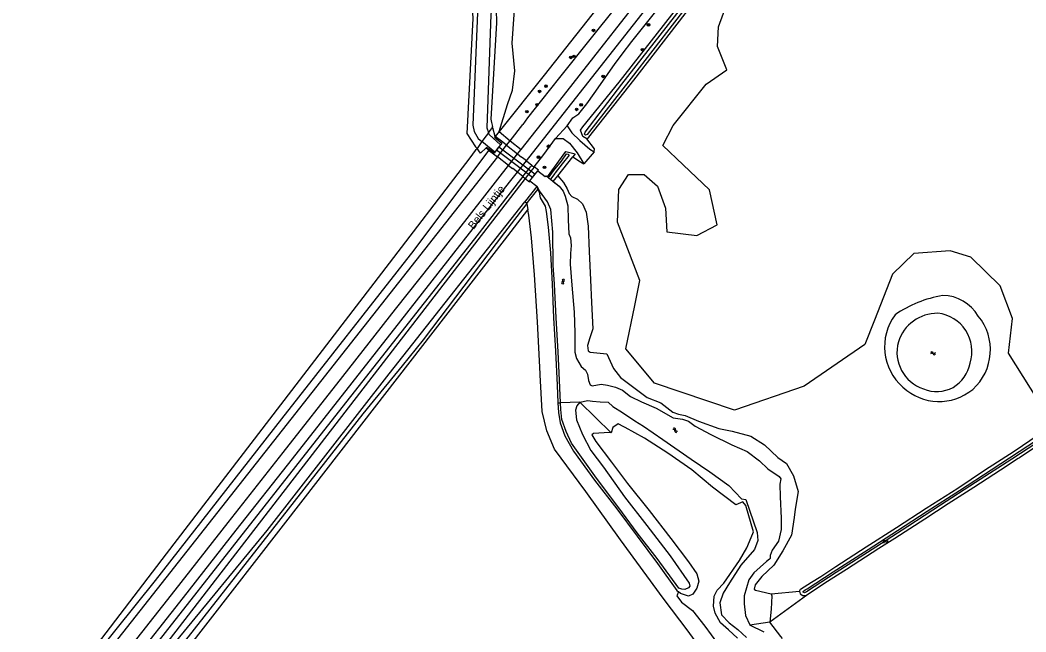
# Model space of a CAD drawing. Extents: x 126000 to 131009, y 393000 to 395500.
# Drawn here: x 129887 to 130201.2, y 393741.6 to 393932.5 of the extents above; entities that cross this region are included whole.
import ezdxf

# ---------------------------------------------------------------- set-up
doc = ezdxf.new("R2010")
doc.units = 0
for name, color, linetype in [('gg-afsc-hekwerk', 7, 'Continuous'), ('gg-anno-openbare ruimte label', 7, 'Continuous'), ('gg-knt-BGT kruinlijn', 7, 'Continuous'), ('gg-knt-bovenkant onderkant talud', 7, 'Continuous'), ('gg-knt-bronhoudergrens', 7, 'Continuous'), ('gg-kntw-bovenkant insteek waterloop', 7, 'Continuous'), ('gg-kntw-waterlijn', 7, 'Continuous'), ('gg-kwrk-duiker nz vlak', 7, 'Continuous'), ('gt-grn-groengrens', 7, 'Continuous'), ('gt-symb-boom', 7, 'Continuous'), ('gt-symb-watersymbool', 7, 'Continuous'), ('gx-grn-maaiveld', 7, 'Continuous')]:
    doc.layers.add(name, color=color, linetype=linetype)

# ---------------------------------------------------------------- blocks, each defined once
blk = doc.blocks.new('gt0-WA')
at = {"layer": 'gt-symb-watersymbool'}
for centre, start, end in [((-0.32, 0.02), 28.0725, 151.9275), ((0.43, 0.42), 208.0725, 331.9275), ((-0.32, -0.43), 28.0725, 151.9275), ((0.43, -0.03), 208.0725, 331.9275)]:
    blk.add_arc(centre, 0.425, start, end, dxfattribs=at)
blk = doc.blocks.new('gt0-BOOM')
at = {"layer": 'gt-symb-boom'}
for radius in [0.4, 0.2]:
    blk.add_circle((0, 0), radius, dxfattribs=at)

msp = doc.modelspace()

# ---------------------------------------------------------------- linework, layer by layer
at = {"layer": 'gg-afsc-hekwerk'}
msp.add_lwpolyline([(130051.34, 393883.94), (130051.75, 393883.61), (130052.11, 393883.32), (130052.67, 393882.86), (130055.37, 393880.66), (130056.64, 393879.1)], dxfattribs=at)
at = {"layer": 'gg-knt-BGT kruinlijn'}
for p, q in [((130040.05, 393894.86), (130044.1, 393899.99)), ((130038.96, 393893.47), (130040.05, 393894.86)), ((130047.62, 393886.72), (130050.6, 393890.63))]:
    msp.add_line(p, q, dxfattribs=at)
for points in [[(130138.09, 394019.9), (130131.16, 394010.84), (130114.29, 393989.45), (130105.32, 393977.42), (130090.8, 393959.23), (130073.42, 393937.01), (130065.02, 393926.5), (130055.46, 393914.65), (130049.86, 393907.6), (130045.54, 393902.09), (130044.1, 393899.99)], [(130057.95, 393899.52), (130059.66, 393902.02), (130061.58, 393903.28), (130064, 393906.45), (130066.36, 393909.68), (130072.72, 393918.67), (130075.08, 393921.9), (130078.12, 393925.86), (130088.1, 393938.37), (130091.01, 393942.21), (130097.57, 393951.04), (130101.09, 393955.54), (130103.63, 393958.63), (130112.69, 393969.31), (130116.06, 393973.49), (130119.12, 393977.45), (130124.5, 393984.66), (130126.18, 393987.07), (130130.65, 393992.68), (130136.69, 394000)], [(130050.6, 393890.63), (130053.41, 393894.49), (130054.29, 393895.62)]]:
    msp.add_lwpolyline(points, dxfattribs=at)
at = {"layer": 'gg-knt-bovenkant onderkant talud'}
msp.add_line((130036.66, 393897.81), (130035.39, 393896.23), dxfattribs=at)
msp.add_lwpolyline([(130118.81, 394000), (130115.15, 393995.76), (130096.51, 393972.04), (130070.73, 393940.7), (130050.77, 393915.34), (130036.66, 393897.81)], dxfattribs=at)
at = {"layer": 'gg-knt-bronhoudergrens'}
msp.add_line((130132.63, 393752.95), (130121.18, 393744.54), dxfattribs=at)
at = {"layer": 'gg-kntw-bovenkant insteek waterloop'}
for p, q in [((130054.98, 393883.95), (130059.66, 393889.85)), ((130121.18, 393744.54), (130114.98, 393743.66))]:
    msp.add_line(p, q, dxfattribs=at)
for points in [[(130035.75, 393957.53), (130036.53, 393956.65), (130036.98, 393955.01), (130036.61, 393951.98), (130036.17, 393948.76), (130035.76, 393943.89), (130035.64, 393940.12), (130035.88, 393931.7), (130034.05, 393901.58), (130034.31, 393900.54), (130034.62, 393899.31)], [(130028.46, 393946.08), (130027.9, 393943.68), (130028.06, 393940.27), (130028.41, 393933.1), (130026.59, 393897.17), (130029.28, 393893.03), (130029.74, 393892.45)], [(130054.98, 393883.95), (130056.72, 393881.88), (130057.86, 393879.92), (130058.49, 393878.37), (130059.39, 393877.49), (130061.17, 393876.66), (130062.74, 393875.17), (130063.84, 393872.61), (130064.49, 393868.26), (130064.74, 393860.26), (130065.22, 393851.46), (130065.51, 393844.41), (130065.89, 393836.19), (130064.94, 393833.39), (130064.23, 393831), (130064.42, 393829.25), (130065.14, 393828.84), (130070.26, 393828.31), (130072.43, 393823.79), (130074.59, 393820.93), (130078.28, 393818.11), (130082.85, 393814.73), (130087.19, 393813.03), (130090.94, 393810.11), (130092.64, 393809.52), (130094.75, 393809.11), (130098.98, 393807.38), (130105.29, 393805.08), (130109.5, 393804.26), (130115.3, 393802.6), (130119.57, 393799.9), (130123.71, 393795.98), (130126.42, 393794.13), (130128.58, 393790.26), (130130.05, 393785.41), (130129.13, 393779.85), (130128.79, 393777.21), (130128, 393771.74), (130125.25, 393766.89), (130122.43, 393762.38), (130118.71, 393758.81), (130116.63, 393756.28), (130116.3, 393754.85), (130116.75, 393754.56), (130121.6, 393753.42)], [(130125.15, 393739.44), (130124.66, 393740.14), (130121.18, 393744.54)]]:
    msp.add_lwpolyline(points, dxfattribs=at)
for centre, radius, start, end in [((130181.41, 393810.06), 37.04, 99.6668, 124.5988), ((130175.07, 393833.46), 13.11, 30.6386, 89.4589), ((130173.69, 393830.56), 16.64, 143.1147, 229.193), ((130173.58, 393829.62), 16.55, 311.7138, 39.4923), ((130174.09, 393829.85), 16.38, 226.4896, 309.8386)]:
    msp.add_arc(centre, radius, start, end, dxfattribs=at)
at = {"layer": 'gg-kntw-waterlijn'}
for points in [[(130031.7, 393956.37), (130031.56, 393956.32), (130031.42, 393955.8), (130031.25, 393954.64), (130030.78, 393948.85), (130030.03, 393943.66), (130030.13, 393939.99), (130028.4, 393899.76), (130028.9, 393897.77), (130030.07, 393895.59), (130031.27, 393894.6)], [(130034.13, 393956.26), (130034.36, 393956.03), (130034.47, 393955.58), (130034.5, 393951.83), (130034.27, 393947.73), (130034.54, 393945.17), (130034.89, 393940.03), (130034.07, 393934.27), (130032.84, 393898.95), (130033.32, 393897.49)], [(130119.45, 393741.49), (130114.98, 393743.66)]]:
    msp.add_lwpolyline(points, dxfattribs=at)
for centre, radius, start, end in [((130173.59, 393828.2), 12.82, 89.5976, 162.3414), ((130172.45, 393829.18), 11.91, 341.7727, 84.0579), ((130173.06, 393828.89), 12.12, 164.7095, 251.5079), ((130173.34, 393827.1), 10.54, 246.9709, 350.995)]:
    msp.add_arc(centre, radius, start, end, dxfattribs=at)
at = {"layer": 'gg-kwrk-duiker nz vlak'}
for points in [[(130047.12, 393883.44), (130035.79, 393891.96), (130036.52, 393892.92)], [(130047.12, 393883.44), (130047.84, 393884.4), (130036.52, 393892.92)]]:
    msp.add_lwpolyline(points, dxfattribs=at)
at = {"layer": 'gt-grn-groengrens'}
msp.add_line((130036.66, 393897.81), (130040.05, 393894.86), dxfattribs=at)
for points in [[(130036.66, 393897.81), (130039.22, 393906.16), (130040.78, 393910.71), (130041.58, 393916.72), (130040.76, 393925.36), (130043.32, 393962.81)], [(130211.29, 393803.86), (130195.8, 393828.6), (130197.05, 393839.41), (130193.22, 393849.59), (130183.99, 393858.56), (130177.55, 393860.53), (130166.19, 393859.72), (130159.58, 393853.28), (130153.89, 393838.85), (130150.92, 393831.3), (130131.9, 393818.3), (130110.14, 393810.74), (130085.19, 393819.22), (130076.27, 393829.87), (130079.02, 393843.49), (130080.59, 393851.24), (130073.61, 393869.49), (130074.08, 393879.67), (130077.05, 393884.37), (130081.91, 393884.34), (130086.1, 393880.71), (130088.66, 393873.81), (130089.02, 393866.45), (130098.42, 393865.27), (130104.81, 393868.59), (130102.36, 393879.58), (130094.17, 393887.33), (130087.79, 393893.37), (130091.01, 393899.67), (130101.35, 393912.51), (130107.76, 393917.05), (130104.84, 393924.35), (130105.17, 393930.42), (130107.85, 393937.85)]]:
    msp.add_lwpolyline(points, dxfattribs=at)
at = {"layer": 'gx-grn-maaiveld'}
for p, q in [((130054.29, 393895.62), (130057.95, 393899.52)), ((130031.27, 393894.6), (130029.74, 393892.45)), ((130035.27, 393891.3), (130031.27, 393894.6)), ((130037.04, 393893.58), (130035.27, 393891.3)), ((130037.76, 393894.4), (130035.39, 393896.23)), ((130038.96, 393893.47), (130037.76, 393894.4)), ((130038.96, 393893.47), (130042.42, 393890.76)), ((130040.05, 393894.86), (130043.52, 393892.12)), ((130034.92, 393890.79), (130036.12, 393889.86)), ((130039.6, 393887.16), (130042.44, 393890.75)), ((130042.44, 393890.75), (130042.42, 393890.76)), ((130042.44, 393890.75), (130043.52, 393892.12)), ((130042.44, 393890.75), (130043.68, 393889.78)), ((130066.35, 393891.44), (130063.11, 393887.68)), ((130036.12, 393889.86), (129880.22, 393692.1)), ((130039.6, 393887.16), (130036.12, 393889.86)), ((130039.6, 393887.16), (130040.87, 393886.18)), ((130039.6, 393887.16), (130039.6, 393887.16)), ((130042.35, 393885.03), (130045.18, 393888.61)), ((130043.69, 393889.78), (130043.68, 393889.78)), ((130045.17, 393888.5), (130045.23, 393888.57)), ((130046.83, 393887.2), (130045.17, 393888.5)), ((130045.21, 393888.59), (130045.18, 393888.61)), ((130045.23, 393888.58), (130045.21, 393888.59)), ((130045.23, 393888.57), (130045.23, 393888.58)), ((130042.41, 393884.98), (130042.35, 393885.03)), ((130048.95, 393885.68), (130047.62, 393886.72)), ((130053.55, 393882.14), (130054.98, 393883.95)), ((130044.1, 393883.67), (130044.82, 393883.11)), ((130044.82, 393883.11), (130046.12, 393882.1)), ((130046.12, 393882.1), (130046.28, 393882.3)), ((130048.45, 393880.57), (130046.28, 393882.3)), ((130051.75, 393883.61), (130052.11, 393883.32)), ((130052.11, 393883.32), (130052.67, 393882.86)), ((130052.67, 393882.86), (130053.55, 393882.14)), ((130048.6, 393880.45), (130048.45, 393880.57)), ((130048.71, 393879.7), (130048.6, 393880.45)), ((130045.29, 393875.32), (130044.71, 393875.83)), ((130045.29, 393875.32), (130045.66, 393873.32)), ((130055.03, 393813.09), (130055.83, 393813.11)), ((130061.88, 393813.26), (130055.83, 393813.11)), ((130061.88, 393813.26), (130071.67, 393803.7)), ((130121.6, 393753.42), (130130.47, 393754.22))]:
    msp.add_line(p, q, dxfattribs=at)
for points in [[(130045.18, 393888.61), (130051.7, 393896.86), (130094.04, 393950.74), (130218.22, 394108.45), (130343.52, 394267.78), (130352.02, 394278.84), (130359.87, 394289.49), (130367.63, 394300.9), (130375.09, 394312.48), (130382.3, 394324.57), (130388.46, 394335.64), (130391.13, 394340.65), (130392.06, 394342.07)], [(130043.52, 393892.12), (130053.33, 393904.54), (130090.91, 393952.46), (130139.38, 394014.01)], [(130144.2, 394000.61), (130139.77, 393994.95), (130137.91, 393991.89), (130125.28, 393975.68), (130077.89, 393914.43), (130064.19, 393896.82), (130063.67, 393896.63), (130063.34, 393896.99), (130063.5, 393897.61), (130074.95, 393912.6), (130093.31, 393935.99), (130107.66, 393954.98), (130123.41, 393974.74), (130139.93, 393996.11), (130142.64, 393999.39)], [(130064.07, 393895.5), (130064.02, 393895.45), (130062.85, 393896.23), (130062.06, 393898.23), (130062.78, 393899.24), (130074.16, 393913.21), (130092.51, 393936.6), (130106.87, 393955.59), (130122.62, 393975.36), (130139.15, 393996.73), (130141.85, 394000)], [(130064.07, 393895.5), (130064.71, 393896.05), (130078.68, 393913.81), (130126.07, 393975.06), (130138.73, 393991.32), (130140.6, 393994.38), (130144.99, 394000)], [(130033.32, 393897.49), (130032.97, 393896.99), (130032.2, 393895.91), (130031.99, 393895.61), (130031.27, 393894.6)], [(130034.62, 393899.31), (130034.36, 393898.96), (130034.22, 393898.74), (130033.76, 393898.11), (130033.32, 393897.49)], [(130037.04, 393893.58), (130033.55, 393896.8), (130033.32, 393897.49)], [(130035.39, 393896.23), (130034.72, 393898.91), (130034.62, 393899.31)], [(130057.95, 393899.52), (130059.39, 393897.35), (130061.9, 393894.97), (130064.98, 393892.27), (130066.35, 393891.44)], [(130035.39, 393896.23), (130035.19, 393896.03), (130037.52, 393894.18), (130037.04, 393893.58)], [(130036.12, 393889.86), (130037.58, 393891.71), (130038.96, 393893.47)], [(130054.29, 393895.62), (130056.61, 393895.61), (130058.62, 393894.08), (130061.08, 393891.09), (130063.11, 393887.68)], [(130066.35, 393891.44), (130066.49, 393892.41), (130064.07, 393895.5)], [(129890.63, 393710.88), (129895.57, 393715.66), (129897.94, 393718.55), (129929.25, 393757.61), (129968.78, 393808.11), (130010.14, 393860.71), (130033.48, 393891.87), (130033.5, 393891.9)], [(130027.59, 393889.6), (130029.3, 393891.84), (130029.5, 393892.11), (130029.74, 393892.45)], [(130032.59, 393892.62), (130030.87, 393891.04), (130029.74, 393892.45)], [(130035.27, 393891.3), (130035.05, 393891.02), (130032.69, 393892.8), (130032.59, 393892.62)], [(130032.59, 393892.62), (130033.5, 393891.91), (130033.5, 393891.9)], [(130033.5, 393891.9), (130033.51, 393891.9), (130033.68, 393891.77), (130034.92, 393890.79)], [(130051.75, 393883.61), (130057.46, 393891.51), (130060.43, 393890.82), (130059.66, 393889.85)], [(130052.11, 393883.32), (130053.59, 393885.53), (130056.09, 393888.5), (130057.71, 393890.82), (130058.23, 393890.71), (130058.49, 393890.4), (130056.36, 393887.63), (130054.2, 393884.83), (130054.09, 393884.68), (130052.67, 393882.86)], [(129746.15, 393517.2), (129752.57, 393525.42), (129758.18, 393532.42), (129763.9, 393538.96), (129770.56, 393545.81), (129775.78, 393551.39), (129781.8, 393558.86), (129788.29, 393566.98), (129805.74, 393589.29), (129821.58, 393609.46), (129837.17, 393629.36), (129851.57, 393647.75), (129869.54, 393670.61), (129886.18, 393691.83), (129901.89, 393711.93), (129918.51, 393733.02), (129935.43, 393754.56), (129952.04, 393775.74), (129969.2, 393797.57), (129987.87, 393821.33), (130004.31, 393842.28), (130019.22, 393861.16), (130036.22, 393882.86), (130039.6, 393887.16)], [(129890.63, 393710.88), (129932.78, 393765.88), (129971.85, 393816.88), (129985.25, 393834.34), (130000, 393853.59), (130027.59, 393889.6)], [(130045.18, 393888.61), (130043.99, 393889.53), (130043.99, 393889.53), (130043.69, 393889.78)], [(130044.1, 393883.67), (130045.82, 393885.89), (130046.46, 393886.73), (130046.83, 393887.2)], [(130046.83, 393887.2), (130047.09, 393887.01), (130047.56, 393886.64)], [(130059.66, 393889.85), (130062.04, 393888.3), (130063.11, 393887.68)], [(129778.4, 393549.14), (129780.62, 393551.89), (129782.17, 393553.8), (129787.28, 393560.18), (129789.61, 393563.06), (129791.1, 393564.9), (129803.39, 393580.6), (129807.79, 393586.23), (129823.65, 393606.45), (129840.04, 393627.38), (129854.67, 393645.97), (129870.51, 393666.22), (129887.19, 393687.43), (129904.32, 393709.36), (129921.52, 393731.22), (129938.1, 393752.3), (129954.52, 393773.26), (129972.1, 393795.6), (129990.74, 393819.33), (130005.9, 393838.68), (130022.55, 393859.78), (130039.9, 393881.93), (130042.35, 393885.03)], [(130042.35, 393885.03), (130040.88, 393886.17), (130040.87, 393886.18)], [(130044.1, 393883.67), (130042.47, 393884.93), (130042.41, 393884.98)], [(130047.56, 393886.64), (130047.08, 393886.03), (130046.57, 393885.36), (130044.82, 393883.11)], [(130046.28, 393882.3), (130046.25, 393882.33), (130048.72, 393885.51), (130048.78, 393885.47)], [(130047.62, 393886.72), (130047.61, 393886.71), (130047.56, 393886.64)], [(130048.78, 393885.47), (130048.94, 393885.67), (130048.95, 393885.68)], [(130048.78, 393885.47), (130051.06, 393883.73), (130051.34, 393883.94), (130051.75, 393883.61)], [(130044.1, 393883.67), (130028.99, 393864.31), (129982.95, 393805.79), (129902.66, 393703.55), (129878.05, 393671.41), (129849.23, 393634.42), (129843.05, 393626.5), (129801.96, 393573.13), (129779.91, 393547.32)], [(130044.82, 393883.11), (129865.47, 393651.01), (129798.72, 393532.31), (129798.76, 393530.02), (129811.5, 393550.12), (129830.02, 393579.8), (129845.53, 393605.54), (129846.26, 393606.88)], [(130053.55, 393882.14), (130055.37, 393880.66), (130056.64, 393879.1), (130057.29, 393877.61), (130058.1, 393874.57), (130058.24, 393870.17), (130058.44, 393865.8), (130058.92, 393864.57), (130059.12, 393862.14), (130058.93, 393859.7), (130058.86, 393856.4), (130059.36, 393849.83), (130060.07, 393841.36), (130060.34, 393834.9), (130060.27, 393828.87), (130060.85, 393826.93), (130062.3, 393824.39), (130063.64, 393823.22), (130064.27, 393822.05), (130064.6, 393820.04), (130065.1, 393818.66), (130065.69, 393818.34), (130068.48, 393818.84), (130070.53, 393818.58), (130073, 393817.97), (130075.2, 393817.06), (130077.71, 393815.04), (130081.12, 393813.37), (130085.76, 393811.38), (130091.06, 393808.42), (130093.98, 393808), (130095.76, 393807.29), (130097.91, 393805.73), (130102.79, 393803.14), (130109.33, 393799.98), (130114.12, 393797.89), (130118.01, 393794.95), (130120.56, 393792.47), (130124.13, 393790.03), (130124.67, 393789.29), (130124.29, 393787.62), (130124.42, 393783.74), (130124.74, 393777.06), (130124.81, 393773.51), (130123.94, 393769.87), (130121.93, 393767.11), (130121.33, 393765.36), (130121.31, 393764.51), (130121.16, 393764.25), (130120.16, 393763.48), (130116.2, 393759.94), (130114.61, 393757.76), (130113.21, 393752.8), (130113.19, 393750.28), (130113.58, 393746.64), (130114.96, 393743.7), (130114.98, 393743.66)], [(130048.45, 393880.57), (130044.92, 393876.09), (130044.71, 393875.83)], [(130045.29, 393875.32), (130045.78, 393875.97), (130048.71, 393879.7)], [(130055.83, 393813.11), (130055.38, 393822.43), (130055.14, 393828.97), (130054.47, 393839.58), (130053.99, 393850.12), (130053.58, 393856.02), (130053.43, 393866.36), (130052.78, 393873.39), (130051.74, 393875.86), (130049.22, 393879.21), (130048.6, 393880.45)], [(130048.71, 393879.7), (130049.12, 393878.83), (130049.46, 393877.07), (130051.07, 393874.5), (130051.37, 393872.78), (130052.02, 393867.93), (130052.73, 393859.84), (130053.17, 393850.07), (130053.61, 393839.61), (130054.21, 393829.23), (130054.76, 393818.53), (130055.03, 393813.09)], [(129911.21, 393705.86), (129935.99, 393738.86), (129964.23, 393773.23), (130002.26, 393822.07), (130044.71, 393875.83)], [(130045.29, 393875.32), (130038.38, 393866.23), (130012.92, 393832.7), (130006.33, 393824.63), (129996.4, 393812.48), (129994.04, 393809.58), (129939.46, 393740.02), (129938.12, 393738.39), (129937.96, 393738.19), (129926.85, 393724.67), (129913.76, 393708.15), (129911.21, 393705.86)], [(129772.61, 393498.15), (129781.58, 393509), (129790.33, 393519.22), (129796.63, 393526.14), (129807.45, 393541.02), (129815.06, 393552.77), (129829.21, 393573.85), (129869.02, 393641.26), (129874.21, 393650.92), (129881.83, 393662.48), (129892.38, 393676.51), (129897.36, 393684.05), (129907.49, 393697.46), (129917.81, 393710.86), (129938.91, 393735.7), (129975.46, 393782.82), (130038.32, 393863.86), (130045.66, 393873.32)], [(130111.95, 393723.69), (130111.09, 393724.85), (130109.67, 393724.18), (130108.2, 393725.64), (130104.92, 393729.03), (130102.97, 393731.67), (130095.72, 393741.73), (130087.94, 393752.1), (130074.6, 393770.25), (130063.7, 393785.33), (130053.91, 393798.61), (130051.58, 393804.33), (130050.1, 393810.36), (130049.52, 393821.84), (130049.5, 393822.14), (130048.67, 393838.3), (130047.72, 393853.01), (130046.77, 393864.6), (130046.17, 393869.86), (130045.97, 393871.64), (130045.66, 393873.32)], [(130055.03, 393813.09), (130055.18, 393810.07), (130055.71, 393806.83), (130057.18, 393802.79), (130059.9, 393798), (130066.47, 393788.96), (130073.43, 393779.95), (130086.13, 393762.88), (130092.19, 393754.43), (130092.64, 393754.06)], [(130061.88, 393813.26), (130060.88, 393812.14), (130060.5, 393810.79), (130060.86, 393807.73), (130062.65, 393803.18), (130065.3, 393798.2), (130069.21, 393793.02), (130075.84, 393783.75), (130082.84, 393774.71), (130090.05, 393765.25), (130096.02, 393756.74), (130096.2, 393755.8), (130095.84, 393755.3), (130094.63, 393754.75), (130093.68, 393754.93), (130092.76, 393755.18), (130085.97, 393764.49), (130079.76, 393772.49), (130074.04, 393780.32), (130067.11, 393789.57), (130059.27, 393800.49), (130057.58, 393804.11), (130056.2, 393807.85), (130055.93, 393811), (130055.83, 393813.11)], [(130061.88, 393813.26), (130064.33, 393813.74), (130065.84, 393813.57), (130068.18, 393813.35), (130070.75, 393813.27), (130072.21, 393811.93), (130075.2, 393810), (130079.02, 393807.48), (130081.74, 393805.73), (130087.84, 393801.56), (130096.63, 393795.42), (130102.43, 393791.49), (130108.39, 393787.21), (130112.33, 393783.07), (130113.67, 393782.85), (130117.22, 393772.55), (130117.46, 393770.09), (130116.38, 393767.28), (130112.21, 393762.42), (130108.66, 393756.88), (130106.64, 393753.65), (130105.61, 393750.65), (130106.17, 393746.91), (130108.54, 393744.41), (130111.21, 393742.26), (130113.95, 393739.84)], [(130111.07, 393739.59), (130108.33, 393742.15), (130105.85, 393744.39), (130104.14, 393747.39), (130103.62, 393749.55), (130103.84, 393752.65), (130104.78, 393754.6), (130106.85, 393756.75), (130111.69, 393763.85), (130114.01, 393767.8), (130115.36, 393771.02), (130116.12, 393772.75), (130113.71, 393781.05), (130112.76, 393782.13), (130110.59, 393781.24), (130103.35, 393786.7), (130096.9, 393792.1), (130089.33, 393797.33), (130082.02, 393802.05), (130075.99, 393805.38), (130075.65, 393805.55), (130073.88, 393806.46), (130072.19, 393805.36), (130071.67, 393803.7)], [(130071.67, 393803.7), (130071.18, 393803.78), (130066.15, 393803.5), (130065.57, 393803.08), (130066.86, 393800.98), (130071.71, 393794.56), (130076.75, 393787.91), (130083.57, 393779.45), (130090.34, 393770.75), (130095.78, 393763.41), (130098.41, 393759.7), (130099, 393757.42), (130098.39, 393755.18), (130097.19, 393753.32), (130095.76, 393752.75), (130093.29, 393753.53), (130092.64, 393754.06)], [(130130.47, 393754.22), (130130.76, 393754.86), (130134.24, 393757.09), (130137.17, 393758.89), (130141.84, 393761.95), (130151.34, 393768.09), (130160.76, 393774.09), (130170.09, 393780.18), (130179.93, 393786.44), (130188.32, 393791.99), (130197.52, 393797.97), (130205.05, 393803.08), (130209.11, 393796.9), (130212.02, 393791.79)], [(130204.65, 393800.6), (130196.79, 393795.49), (130185.43, 393788.16), (130174.52, 393781.09), (130164.34, 393774.47), (130154.29, 393767.95), (130141.97, 393760.04), (130132.65, 393754.04), (130132.04, 393753.76), (130131.65, 393753.97), (130131.59, 393754.2), (130132.29, 393754.68), (130132.85, 393755.04), (130140.98, 393760.26), (130151.91, 393767.26), (130161.07, 393773.18), (130170.4, 393779.21), (130180.45, 393785.71), (130190.34, 393792.15), (130204.83, 393801.66)], [(130204.91, 393799.7), (130199.2, 393795.9), (130198.81, 393795.68), (130193.32, 393792.05), (130184.98, 393786.64), (130176.94, 393781.49), (130169.64, 393776.76), (130160.25, 393770.73), (130155.32, 393767.57), (130145.16, 393761.07), (130138.39, 393756.79), (130132.63, 393752.95)], [(130092.64, 393754.06), (130092.16, 393752.78), (130093.6, 393750.82), (130097.02, 393748.24), (130100.93, 393743.36), (130106.84, 393735.26), (130113.48, 393725.68), (130132.19, 393702.55), (130137.04, 393693.86)], [(130121.6, 393753.42), (130121.8, 393752.77), (130121.63, 393748.61), (130121.18, 393744.54)], [(130130.47, 393754.22), (130130.71, 393753.38), (130131.54, 393752.9), (130132.63, 393752.95)]]:
    msp.add_lwpolyline(points, dxfattribs=at)

# ---------------------------------------------------------------- block references
at = {"layer": 'gt-symb-boom'}
for p in [(130083.33, 393931.09), (130066.15, 393929.33), (130060.04, 393921.25), (130081.41, 393923.31), (130059.05, 393920.91), (130069.15, 393914.97), (130051.3, 393911.93), (130049.29, 393910.29), (130048.47, 393906.12), (130062.3, 393906.11), (130045.34, 393903.95), (130060.86, 393904.67), (130052.06, 393893.16), (130048.94, 393889.76), (130050.82, 393886.58)]:
    msp.add_blockref('gt0-BOOM', p, dxfattribs=at)
at = {"layer": 'gt-symb-watersymbool'}
for p, rotation in [((130056.6, 393850.97), -86.3879250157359), ((130172.25, 393828.53), 180), ((130091.62, 393804.53), -34.53212456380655), ((130157.28, 393769.8), 32.752439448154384)]:
    msp.add_blockref('gt0-WA', p, dxfattribs=dict(at, rotation=rotation))

# ---------------------------------------------------------------- texts
at = {"layer": 'gg-anno-openbare ruimte label'}
msp.add_text('Bels Lijntje', height=2.5, rotation=51.8, dxfattribs=at).set_placement((130028.66, 393867.02))

doc.saveas('drawing.dxf')
